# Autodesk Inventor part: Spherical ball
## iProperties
Shininess: 100.0
Angle Display Precision: 2
Document Length Units: 11269
Document Angle Units: 11279
Document Time Units: 11290
Document Mass Units: 11283
Document Length Units Precision: 3
Document Angle Units Precision: 2
Compacted: True
Created: 2001-08
Part Number: Spherical ball
Document SubType Name: Modeling
Designer: Martin Budgell
Density: 0.0
Volumn: 0.0
Area: 0.0
PropertySet Name: Model Information
Control State: 0
Master: False
Checked Out: False
Author: Martin Budgell
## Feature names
1. Revolution1
2. Extrusion1
3. Mirror1
4. Hole1
